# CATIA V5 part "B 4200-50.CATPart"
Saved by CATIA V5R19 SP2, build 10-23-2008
Part number: B 4200-50
Bounding box of the stored display mesh (mm): x -47.487 to 47.487, y -47.487 to 47.487, z 0 to 220
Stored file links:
  C:\Users\Bora\Desktop\3D Katı model\B serisi\B 4200\B 4200-50.CATPart
  C:\Program Files\Dassault Systemes\B19\intel_a\reffiles\standard\MetricThickPitch.txt
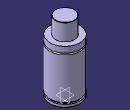
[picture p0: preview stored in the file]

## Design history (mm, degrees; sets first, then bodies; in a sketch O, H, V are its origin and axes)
Body1 (main body)
  Sketch1 on yz-plane, origin (0, 0, 0), H (0, 1, 0), V (0, 0, 1)
    point P1 (47.5, 148.5)
    point P2 (47.5, 143.5)
    point P3 (47.5, 148.5)
    point P6 (47.5, 143.5)
    point P9 (30, 219)
    point P11 (30, 219)
    arc A1 centre (47.5, 146) radius 2.5 from (47.5, 148.5) to (47.5, 143.5) ccw
    line L1 (47.5, 148.5) -> (47.5, 167)
    line L2 (47.5, 13) -> (47.5, 143.5)
    line L3 (43.5, 13) -> (43.5, 8)
    arc A2 centre (29, 219) radius 1 from (30, 219) to (29, 220) ccw
    line L4 (30, 219) -> (30, 167)
    line L5 (47.5, 0) -> (47.5, 8)
    line L6 (29, 220) -> (0, 220)
    point P15 (0, 220)
    line L7 (30, 167) -> (47.5, 167)
    line L8 (0, 0) -> (47.5, 0)
    line L9 (43.5, 13) -> (47.5, 13)
    line L10 (43.5, 8) -> (47.5, 8)
    coincidence: P15 V, P1 P3, P2 P6, P9 P11
    tangency: L6 A2
    horizontal: L7 H, L8 H, L9 H, L10 H
  Shaft1: profile Sketch1, axis Sketch1.V, angle 360
  Sketch2 on face of Shaft1 from Sketch1.L8, origin (0, 0, 0), H (1, 0, 0), V (0, -1, 0)
    point P1 (30, 0)
    distance P1 V = 30
  Hole1: placed by Sketch2, at (30, 0, 0) direction (0, 0, 1), diameter 6.647, depth 13, threaded "M8", thread diameter 8, thread depth 13, pitch 1.25
  CircPattern1: of Hole1, instances 4, angular step 90, axis from xy-plane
